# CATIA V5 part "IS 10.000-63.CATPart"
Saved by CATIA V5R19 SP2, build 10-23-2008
Part number: IS 10.000-63
Bounding box of the stored display mesh (mm): x -97.324 to 97.324, y -97.5 to 97.5, z 0 to 287
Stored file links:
  C:\Users\Bora\Desktop\3D Katı model\IS serisi\IS 10.000\IS 10.000-63.CATPart
  C:\Program Files\Dassault Systemes\B19\intel_a\reffiles\standard\MetricThickPitch.txt
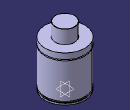
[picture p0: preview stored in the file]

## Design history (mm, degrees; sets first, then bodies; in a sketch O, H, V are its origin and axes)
Body1 (main body)
  Sketch1 on yz-plane, origin (0, 0, 0), H (0, 1, 0), V (0, 0, 1)
    point P1 (97.5, 193)
    point P2 (97.5, 188)
    point P5 (47.5, 286)
    point P7 (47.5, 286)
    point P12 (97.5, 188)
    point P13 (97.5, 193)
    arc A1 centre (97.5, 190.5) radius 2.5 from (97.5, 193) to (97.5, 188) ccw
    line L1 (97.5, 0) -> (97.5, 8)
    line L2 (47.5, 286) -> (47.5, 221)
    arc A2 centre (46.5, 286) radius 1 from (47.5, 286) to (46.5, 287) ccw
    line L3 (93.5, 16) -> (93.5, 8)
    line L4 (97.5, 16) -> (97.5, 188)
    line L5 (97.5, 193) -> (97.5, 221)
    line L6 (46.5, 287) -> (0, 287)
    point P15 (0, 287)
    line L7 (47.5, 221) -> (97.5, 221)
    line L8 (93.5, 16) -> (97.5, 16)
    line L9 (93.5, 8) -> (97.5, 8)
    line L10 (97.5, 0) -> (0, 0)
    tangency: L6 A2
    coincidence: P15 V, P1 P13, P2 P12, P5 P7
    horizontal: L7 H, L8 H, L9 H, L10 H
  Shaft1: profile Sketch1, axis Sketch1.V, angle 360
  Sketch2 on face of Shaft1 from Sketch1.L10, origin (0, 0, 0), H (1, 0, 0), V (0, -1, 0)
    point P1 (60, 0)
    distance P1 V = 60
  Hole1: placed by Sketch2, at (60, 0, 0) direction (0, 0, 1), diameter 10.106, depth 16, threaded "M12", thread diameter 12, thread depth 16, pitch 1.75
  CircPattern1: of Hole1, instances 4, angular step 90, axis from xy-plane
